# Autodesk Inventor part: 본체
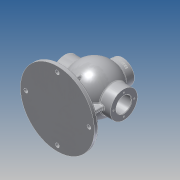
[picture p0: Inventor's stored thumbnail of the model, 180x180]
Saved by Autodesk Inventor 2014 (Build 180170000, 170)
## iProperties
Created: 2020-08
Part Number: 본체
Material: 알루미늄 6061
Document SubType Name: Modeling
Designer: kb542-17
Density: 2.71 g/cm^3
Appearance: 알루미늄 - 평지
Mass: 1759.18 g
Surface Area: 1342.51 cm^2
Volume: 649.144 cm^3
Author: kb542-17
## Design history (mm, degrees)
sketch "스케치1"
  geometry: L1 (-53, 0)-(53, 0); A1 r 53 centre (0, 0) between (53, 0) and (-53, 0); 1 further point
  constraints: 2 end point, 2 point on circle, 1 centre point, 1 coincident, 1 horizontal, 1 midpoint
  dimensions: "d6" = 53 radius of A1
revolve "회전1" sketch "스케치1" stored, may be unused: angle "d1" = 90 deg
sketch "스케치2"
  geometry: L1 (-43, 0)-(43, 0); A1 r 43 centre (0, 0) between (43, 0) and (-43, 0); 1 further point
  constraints: 2 end point, 2 point on circle, 1 centre point, 1 coincident, 1 horizontal, 1 midpoint
  dimensions: "d7" = 43 radius of A1
revolve "회전2" sketch "스케치2" stored, may be unused: angle "d3" = 90 deg
node "작업 평면2"
sketch "스케치6"
  geometry: C1 r 31 at (0, 0); 1 further point
  constraints: 1 centre point, 1 coincident
  dimensions: "d9" = 62 diameter of C1
extrude "돌출1" join sketch "스케치6" stored distance "d10" = 10; taper "d11" = 0 deg
sketch "스케치7"
  geometry: C1 r 31 at (0, 0) reference; 1 further point
  constraints: 1 vertical alignment
  dimensions: "d12" = 24 distance of point (0, 24) C1.centre
hole "구멍1" sketch "스케치7" at (0, 24) diameter "d13" = 3.242; stored, may be unused: countersink angle "d17" = 90 deg, drill point angle "d19" = 118 deg; dims "d14" = 12, "d15" = 4, "d16" = 2, "d18" = 15
sketch "스케치9"
  geometry: C1 r 31 at (0, 0) reference; C2 r 17.5 at (0, 0)
  constraints: 1 centre point, 1 coincident
  dimensions: "d23" = 35 diameter of C2
extrude "돌출2" cut sketch "스케치9" stored distance "d24" = 10; taper "d25" = 0 deg
node "작업 평면3"
sketch "스케치10"
  geometry: C1 r 27 at (0, 0); 1 further point
  constraints: 1 centre point, 1 coincident
  dimensions: "d27" = 54 diameter of C1
extrude "돌출3" join sketch "스케치10" stored distance "d28" = 10; taper "d29" = 0 deg
sketch "스케치11"
  geometry: C1 r 27 at (0, 0) reference; 1 further point
  constraints: 1 vertical alignment
  dimensions: "d30" = 20 distance of point (0, 20) C1.centre
hole "구멍2" sketch "스케치11" at (0, 20) diameter "d31" = 3.242; stored, may be unused: countersink angle "d35" = 90 deg, drill point angle "d37" = 118 deg; dims "d32" = 12, "d33" = 4, "d34" = 2, "d36" = 15
sketch "스케치12"
  geometry: C1 r 27 at (0, 0) reference; C2 r 13 at (0, 0)
  constraints: 1 centre point, 1 coincident
  dimensions: "d41" = 26 diameter of C2
extrude "돌출4" cut sketch "스케치12" stored distance "d42" = 10; taper "d43" = 0 deg
node "작업 평면4"
sketch "스케치14"
  geometry: C1 r 18.5 at (0, 0); C2 r 17.5 at (0, 0) reference; 1 further point
  constraints: 1 centre point, 1 coincident
  dimensions: "d45" = 37 diameter of C1
extrude "돌출5" cut sketch "스케치14" distance "d46" = 1.75; taper "d47" = 0 deg
node "작업 평면5"
sketch "스케치16"
  geometry: C1 r 85 at (0, 0); 1 further point
  constraints: 1 centre point, 1 coincident
  dimensions: "d49" = 170 diameter of C1
extrude "돌출6" join sketch "스케치16" distance "d50" = 10; taper "d51" = 0 deg
sketch "스케치17"
  geometry: C1 r 85 at (0, 0) reference; A1 r 72.5 centre (0, 0) between (0, 72.5) and (72.5, 0); 2 further points
  constraints: 4 point on circle, 2 horizontal alignment, 2 vertical alignment, 1 centre point, 1 coincident
  dimensions: "d52" = 145 diameter of A1
hole "구멍3" sketch "스케치17" at (0, 72.5), (72.5, 0), (0, -72.5), (-72.5, 0) diameter "d53" = 9; stored, may be unused: countersink angle "d57" = 90 deg, drill point angle "d59" = 118 deg; dims "d54" = 12, "d55" = 4, "d56" = 2, "d58" = 15
sketch "스케치18"
  geometry: L1 (-52, 4)-(52, 4); L2 (52, 4)-(52, -4); L3 (52, -4)-(-52, -4); L4 (-52, -4)-(-52, 4); C1 r 85 at (0, 0) reference; 2 further points
  constraints: 8 end point, 2 midpoint, 2 parallel, 1 horizontal, 1 horizontal alignment, 1 perpendicular, 1 vertical alignment
  dimensions: "d60" = 104 distance of L2.end L3.end; "d61" = 8 distance of L1.end L2.end
extrude "돌출7" join sketch "스케치18" stored distance "d62" = 10; taper "d63" = 0 deg
sketch "스케치19"
  geometry: L1 (-4, -43)-(4, -43); L2 (4, -43)-(4, 43); L3 (4, 43)-(-4, 43); L4 (-4, 43)-(-4, -43); L5 (-4, -43)-(4, 43); L6 (4, -43)-(-4, 43); C1 r 85 at (0, 0) reference
  constraints: 12 end point, 2 midpoint, 2 parallel, 1 horizontal, 1 perpendicular
  dimensions: "d64" = 8 distance of L2.end L3.end; "d65" = 86 distance of L1.end L2.end
extrude "돌출8" join sketch "스케치19" stored distance "d66" = 10; taper "d67" = 0 deg
node "작업 평면6"
sketch "스케치20"
  geometry: L1 (-27, 65)-(27, 65) reference; L2 (-27, 65)-(-27, 45.607) reference; 2 further points
  constraints: 1 other
  dimensions: "d69" = 9 distance from line of point (0, 56) L1; "d70" = 27 distance from line of point (0, 56) L2
feature "엠보싱1" sketch "스케치20" dims "d6" = 53, "d18" = 15, "d71" = 0.5, "d72" = 0
chamfer "모따기1" distance "d73" = 1; stored, may be unused: second distance "d74" = 2, angle "d75" = 45 deg
fillet "모깎기1" dims "d76" = 3
fillet "모깎기2" dims "d77" = 3
node "솔리드1"
pattern_circular "원형 패턴1" dims angle "d21" = 360 deg
mirror "대칭1"
pattern_circular "원형 패턴2" dims angle "d39" = 360 deg
other parameters: "d8" = 68, "d26" = 65, "d44" = -16, "d48" = -85, "d68" = 295.25
